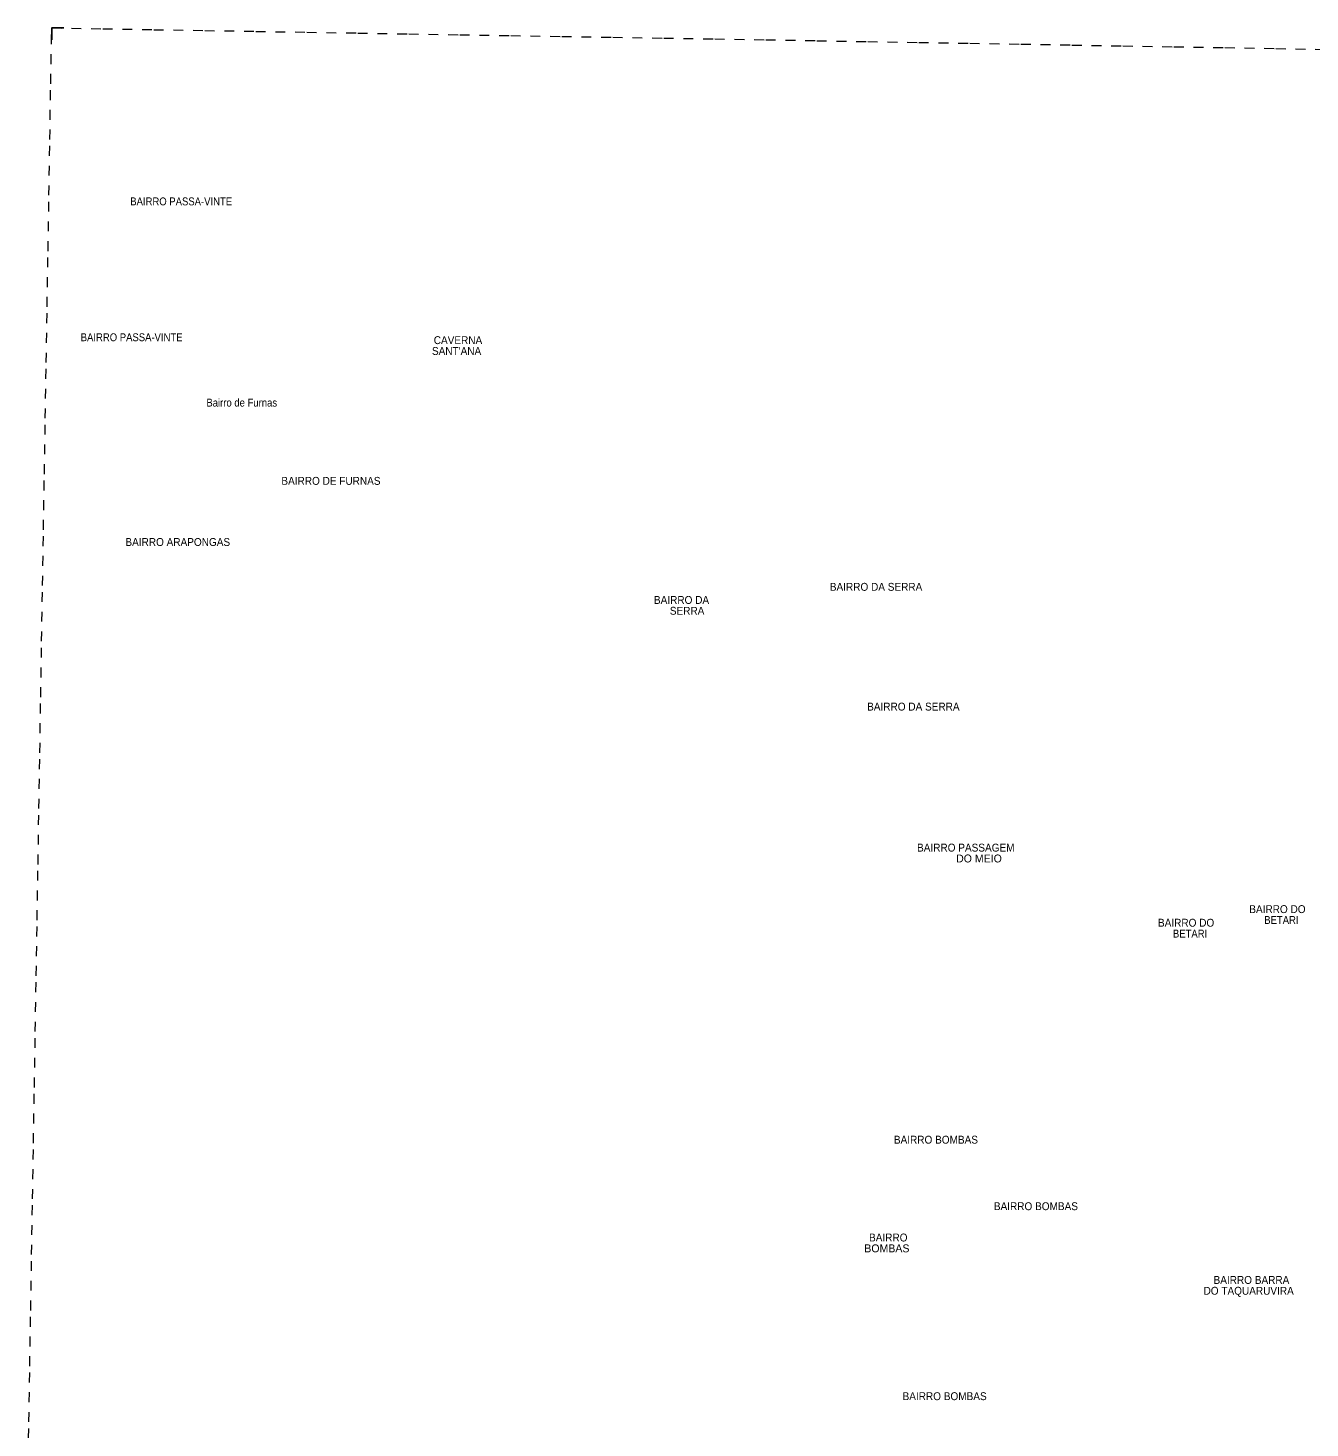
# Model space of a CAD drawing. Extents: x 727.5 to 753.3, y 7260.4 to 7288.5.
# Drawn here: x 727.76 to 740.76, y 7274.36 to 7288.55 of the extents above; entities that cross this region are included whole.
import ezdxf
from ezdxf.enums import TextEntityAlignment as Align

# ---------------------------------------------------------------- set-up
doc = ezdxf.new("R2010")
doc.units = 0
doc.header["$LTSCALE"] = 0.032
doc.linetypes.add('SHORT_DASHED', pattern=[2.7, 1.5, -1.2])
doc.layers.add('46', color=7, linetype='SHORT_DASHED', lineweight=13)
doc.layers.add('63', color=7, linetype='Continuous', lineweight=25)
doc.layers.add('61', color=7, linetype='Continuous')

msp = doc.modelspace()

# ---------------------------------------------------------------- linework, layer by layer
at = {"layer": '46'}
for points in [[(727.7565, 7273.853), (727.7657, 7274.4182), (727.775, 7274.9834), (727.7842, 7275.5486), (727.7935, 7276.1138), (727.8027, 7276.679), (727.812, 7277.2442), (727.8212, 7277.8094), (727.8305, 7278.3746), (727.8397, 7278.9398), (727.849, 7279.505), (727.8582, 7280.0702), (727.8674, 7280.6354), (727.8767, 7281.2006), (727.8859, 7281.7658), (727.8951, 7282.331), (727.9044, 7282.8962), (727.9136, 7283.4614), (727.9228, 7284.0266), (727.932, 7284.5918), (727.9412, 7285.157), (727.9505, 7285.7222), (727.9597, 7286.2874), (727.9689, 7286.8526), (727.9781, 7287.4178), (727.9873, 7287.983), (727.9965, 7288.5482)], [(727.9965, 7288.5482), (728.5137, 7288.5397), (729.0309, 7288.5313), (729.5481, 7288.5228), (730.0652, 7288.5143), (730.5824, 7288.5058), (731.0996, 7288.4973), (731.6168, 7288.4887), (732.134, 7288.4801), (732.6512, 7288.4716), (733.1683, 7288.4629), (733.6855, 7288.4543), (734.2027, 7288.4457), (734.7199, 7288.437), (735.2371, 7288.4283), (735.7543, 7288.4196), (736.2715, 7288.4109), (736.7887, 7288.4022), (737.3059, 7288.3934), (737.8231, 7288.3846), (738.3403, 7288.3758), (738.8575, 7288.367), (739.3747, 7288.3582), (739.8919, 7288.3493), (740.4091, 7288.3404), (740.9263, 7288.3315)]]:
    msp.add_lwpolyline(points, dxfattribs=at)
at = {"layer": '63'}
msp.add_lwpolyline([(728.1199, 7288.5482), (727.9967, 7288.5482), (727.9967, 7288.4268)], dxfattribs=at)

# ---------------------------------------------------------------- texts
at = {"layer": '61'}
for s, width, p in [('BAIRRO PASSA-VINTE', 0.9, (729.30995, 7286.7506)), ('BAIRRO PASSA-VINTE', 0.9, (728.80735, 7285.3732)), (' CAVERNA', 0.95, (732.1023, 7285.344)), ("SANT'ANA", 0.95, (732.1023, 7285.234)), ('BAIRRO DE FURNAS', 0.95, (730.8284, 7283.9176)), ('BAIRRO ARAPONGAS', 0.95, (729.27525, 7283.2977)), ('BAIRRO DA SERRA', 0.95, (736.35555, 7282.8433)), ('BAIRRO DA', 0.95, (734.383, 7282.7104)), ('    SERRA', 0.95, (734.38295, 7282.6004)), ('BAIRRO DA SERRA', 0.95, (736.73355, 7281.6291)), ('BAIRRO PASSAGEM', 0.95, (737.26525, 7280.1996)), ('BAIRRO DO', 0.95, (740.4251, 7279.5762)), ('   BETARI', 0.9, (740.4251, 7279.4662)), ('BAIRRO DO', 0.95, (739.4992, 7279.4382)), ('   BETARI', 0.9, (739.4992, 7279.3282)), ('BAIRRO BOMBAS', 0.95, (736.9626, 7277.239)), ('BAIRRO BOMBAS', 0.95, (737.9763, 7276.5647)), (' BAIRRO', 0.95, (736.46505, 7276.2474)), ('  BAIRRO BARRA', 0.95, (740.13335, 7275.8174)), ('DO TAQUARUVIRA', 0.95, (740.1334, 7275.7074)), ('BAIRRO BOMBAS', 0.95, (737.0506, 7274.6389))]:
    msp.add_text(s, height=0.08, dxfattribs=dict(at, width=width)).set_placement(p, align=Align.CENTER)
at = {"layer": '61', "width": 0.9}
msp.add_text('Bairro de Furnas', height=0.08, dxfattribs=at).set_placement((730.2824, 7284.7107), align=Align.RIGHT)
at = {"layer": '61'}
for s, p in [('         DO MEIO', (737.2652, 7280.0896)), ('BOMBAS', (736.46505, 7276.1374))]:
    msp.add_text(s, height=0.08, dxfattribs=at).set_placement(p, align=Align.CENTER)

doc.saveas('drawing.dxf')
